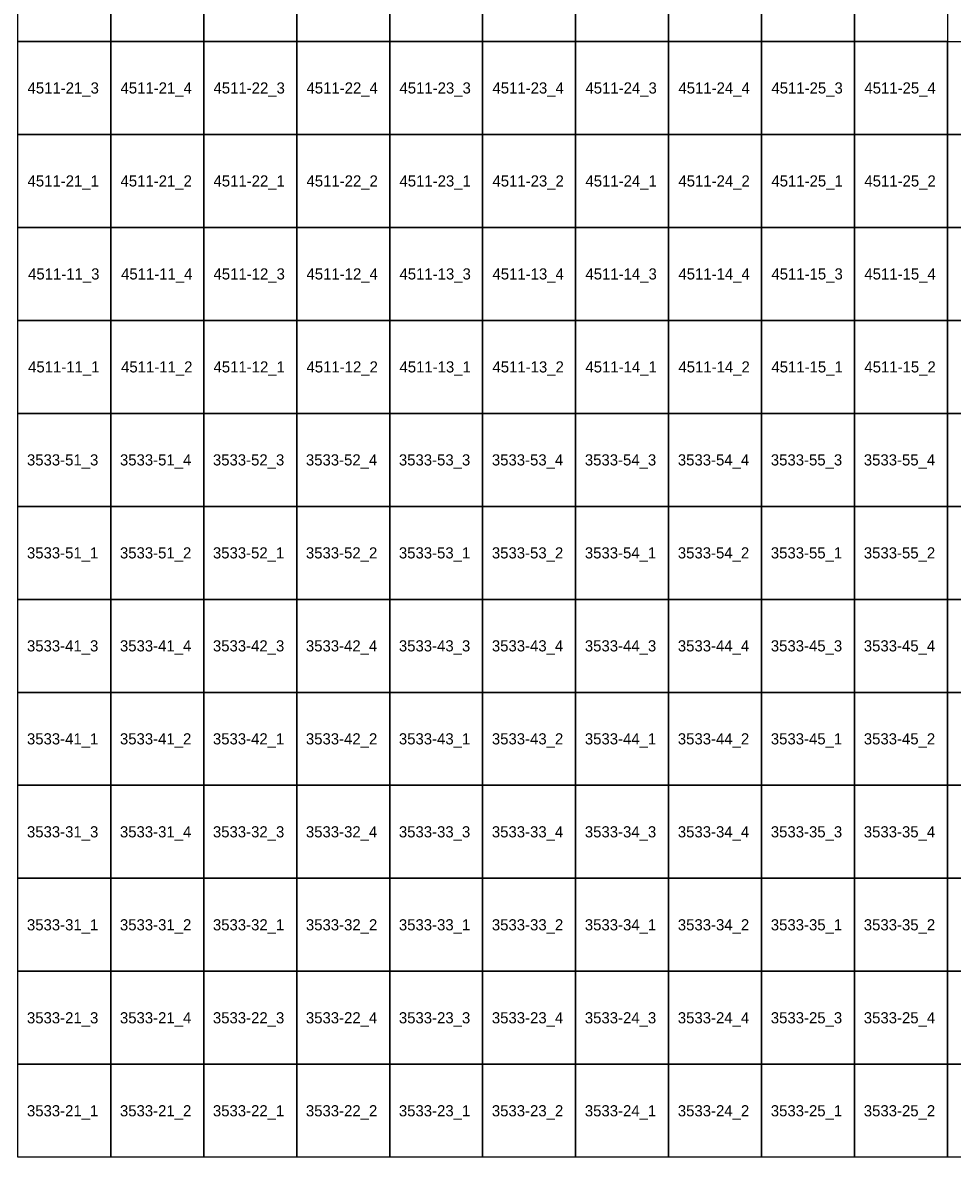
# Model space of a CAD drawing. Extents: x 312500 to 765000, y 172500 to 440000.
# Drawn here: x 700132 to 725129, y 280078 to 310507 of the extents above; entities that cross this region are included whole.
import ezdxf

# ---------------------------------------------------------------- set-up
doc = ezdxf.new("R2010")
doc.units = 0
doc.layers.add('Topo5_ramis_TKS2025', color=7, linetype='Continuous')
doc.layers.add('Topo5_ramis_TKS2025_Nr', color=7, linetype='Continuous')

msp = doc.modelspace()

# ---------------------------------------------------------------- linework, layer by layer
at = {"layer": 'Topo5_ramis_TKS2025'}
for points in [[(700000, 310000), (700000, 312500), (702500, 312500), (702500, 310000), (700000, 310000)], [(702500, 310000), (702500, 312500), (705000, 312500), (705000, 310000), (702500, 310000)], [(705000, 310000), (705000, 312500), (707500, 312500), (707500, 310000), (705000, 310000)], [(707500, 310000), (707500, 312500), (710000, 312500), (710000, 310000), (707500, 310000)], [(710000, 310000), (710000, 312500), (712500, 312500), (712500, 310000), (710000, 310000)], [(712500, 310000), (712500, 312500), (715000, 312500), (715000, 310000), (712500, 310000)], [(715000, 310000), (715000, 312500), (717500, 312500), (717500, 310000), (715000, 310000)], [(717500, 310000), (717500, 312500), (720000, 312500), (720000, 310000), (717500, 310000)], [(720000, 310000), (720000, 312500), (722500, 312500), (722500, 310000), (720000, 310000)], [(722500, 310000), (722500, 312500), (725000, 312500), (725000, 310000), (722500, 310000)], [(700000, 307500), (700000, 310000), (702500, 310000), (702500, 307500), (700000, 307500)], [(702500, 307500), (702500, 310000), (705000, 310000), (705000, 307500), (702500, 307500)], [(705000, 307500), (705000, 310000), (707500, 310000), (707500, 307500), (705000, 307500)], [(707500, 307500), (707500, 310000), (710000, 310000), (710000, 307500), (707500, 307500)], [(710000, 307500), (710000, 310000), (712500, 310000), (712500, 307500), (710000, 307500)], [(712500, 307500), (712500, 310000), (715000, 310000), (715000, 307500), (712500, 307500)], [(715000, 307500), (715000, 310000), (717500, 310000), (717500, 307500), (715000, 307500)], [(717500, 307500), (717500, 310000), (720000, 310000), (720000, 307500), (717500, 307500)], [(720000, 307500), (720000, 310000), (722500, 310000), (722500, 307500), (720000, 307500)], [(722500, 307500), (722500, 310000), (725000, 310000), (725000, 307500), (722500, 307500)], [(725000, 307500), (725000, 310000), (727500, 310000), (727500, 307500), (725000, 307500)], [(700000, 305000), (700000, 307500), (702500, 307500), (702500, 305000), (700000, 305000)], [(702500, 305000), (702500, 307500), (705000, 307500), (705000, 305000), (702500, 305000)], [(705000, 305000), (705000, 307500), (707500, 307500), (707500, 305000), (705000, 305000)], [(707500, 305000), (707500, 307500), (710000, 307500), (710000, 305000), (707500, 305000)], [(710000, 305000), (710000, 307500), (712500, 307500), (712500, 305000), (710000, 305000)], [(712500, 305000), (712500, 307500), (715000, 307500), (715000, 305000), (712500, 305000)], [(715000, 305000), (715000, 307500), (717500, 307500), (717500, 305000), (715000, 305000)], [(717500, 305000), (717500, 307500), (720000, 307500), (720000, 305000), (717500, 305000)], [(720000, 305000), (720000, 307500), (722500, 307500), (722500, 305000), (720000, 305000)], [(722500, 305000), (722500, 307500), (725000, 307500), (725000, 305000), (722500, 305000)], [(725000, 305000), (725000, 307500), (727500, 307500), (727500, 305000), (725000, 305000)], [(700000, 302500), (700000, 305000), (702500, 305000), (702500, 302500), (700000, 302500)], [(702500, 302500), (702500, 305000), (705000, 305000), (705000, 302500), (702500, 302500)], [(705000, 302500), (705000, 305000), (707500, 305000), (707500, 302500), (705000, 302500)], [(707500, 302500), (707500, 305000), (710000, 305000), (710000, 302500), (707500, 302500)], [(710000, 302500), (710000, 305000), (712500, 305000), (712500, 302500), (710000, 302500)], [(712500, 302500), (712500, 305000), (715000, 305000), (715000, 302500), (712500, 302500)], [(715000, 302500), (715000, 305000), (717500, 305000), (717500, 302500), (715000, 302500)], [(717500, 302500), (717500, 305000), (720000, 305000), (720000, 302500), (717500, 302500)], [(720000, 302500), (720000, 305000), (722500, 305000), (722500, 302500), (720000, 302500)], [(722500, 302500), (722500, 305000), (725000, 305000), (725000, 302500), (722500, 302500)], [(725000, 302500), (725000, 305000), (727500, 305000), (727500, 302500), (725000, 302500)], [(700000, 300000), (700000, 302500), (702500, 302500), (702500, 300000), (700000, 300000)], [(702500, 300000), (702500, 302500), (705000, 302500), (705000, 300000), (702500, 300000)], [(705000, 300000), (705000, 302500), (707500, 302500), (707500, 300000), (705000, 300000)], [(707500, 300000), (707500, 302500), (710000, 302500), (710000, 300000), (707500, 300000)], [(710000, 300000), (710000, 302500), (712500, 302500), (712500, 300000), (710000, 300000)], [(712500, 300000), (712500, 302500), (715000, 302500), (715000, 300000), (712500, 300000)], [(715000, 300000), (715000, 302500), (717500, 302500), (717500, 300000), (715000, 300000)], [(717500, 300000), (717500, 302500), (720000, 302500), (720000, 300000), (717500, 300000)], [(720000, 300000), (720000, 302500), (722500, 302500), (722500, 300000), (720000, 300000)], [(722500, 300000), (722500, 302500), (725000, 302500), (725000, 300000), (722500, 300000)], [(725000, 300000), (725000, 302500), (727500, 302500), (727500, 300000), (725000, 300000)], [(700000, 297500), (700000, 300000), (702500, 300000), (702500, 297500), (700000, 297500)], [(702500, 297500), (702500, 300000), (705000, 300000), (705000, 297500), (702500, 297500)], [(705000, 297500), (705000, 300000), (707500, 300000), (707500, 297500), (705000, 297500)], [(707500, 297500), (707500, 300000), (710000, 300000), (710000, 297500), (707500, 297500)], [(710000, 297500), (710000, 300000), (712500, 300000), (712500, 297500), (710000, 297500)], [(712500, 297500), (712500, 300000), (715000, 300000), (715000, 297500), (712500, 297500)], [(715000, 297500), (715000, 300000), (717500, 300000), (717500, 297500), (715000, 297500)], [(717500, 297500), (717500, 300000), (720000, 300000), (720000, 297500), (717500, 297500)], [(720000, 297500), (720000, 300000), (722500, 300000), (722500, 297500), (720000, 297500)], [(722500, 297500), (722500, 300000), (725000, 300000), (725000, 297500), (722500, 297500)], [(725000, 297500), (725000, 300000), (727500, 300000), (727500, 297500), (725000, 297500)], [(700000, 295000), (700000, 297500), (702500, 297500), (702500, 295000), (700000, 295000)], [(702500, 295000), (702500, 297500), (705000, 297500), (705000, 295000), (702500, 295000)], [(705000, 295000), (705000, 297500), (707500, 297500), (707500, 295000), (705000, 295000)], [(707500, 295000), (707500, 297500), (710000, 297500), (710000, 295000), (707500, 295000)], [(710000, 295000), (710000, 297500), (712500, 297500), (712500, 295000), (710000, 295000)], [(712500, 295000), (712500, 297500), (715000, 297500), (715000, 295000), (712500, 295000)], [(715000, 295000), (715000, 297500), (717500, 297500), (717500, 295000), (715000, 295000)], [(717500, 295000), (717500, 297500), (720000, 297500), (720000, 295000), (717500, 295000)], [(720000, 295000), (720000, 297500), (722500, 297500), (722500, 295000), (720000, 295000)], [(722500, 295000), (722500, 297500), (725000, 297500), (725000, 295000), (722500, 295000)], [(725000, 295000), (725000, 297500), (727500, 297500), (727500, 295000), (725000, 295000)], [(700000, 292500), (700000, 295000), (702500, 295000), (702500, 292500), (700000, 292500)], [(702500, 292500), (702500, 295000), (705000, 295000), (705000, 292500), (702500, 292500)], [(705000, 292500), (705000, 295000), (707500, 295000), (707500, 292500), (705000, 292500)], [(707500, 292500), (707500, 295000), (710000, 295000), (710000, 292500), (707500, 292500)], [(710000, 292500), (710000, 295000), (712500, 295000), (712500, 292500), (710000, 292500)], [(712500, 292500), (712500, 295000), (715000, 295000), (715000, 292500), (712500, 292500)], [(715000, 292500), (715000, 295000), (717500, 295000), (717500, 292500), (715000, 292500)], [(717500, 292500), (717500, 295000), (720000, 295000), (720000, 292500), (717500, 292500)], [(720000, 292500), (720000, 295000), (722500, 295000), (722500, 292500), (720000, 292500)], [(722500, 292500), (722500, 295000), (725000, 295000), (725000, 292500), (722500, 292500)], [(725000, 292500), (725000, 295000), (727500, 295000), (727500, 292500), (725000, 292500)], [(700000, 290000), (700000, 292500), (702500, 292500), (702500, 290000), (700000, 290000)], [(702500, 290000), (702500, 292500), (705000, 292500), (705000, 290000), (702500, 290000)], [(705000, 290000), (705000, 292500), (707500, 292500), (707500, 290000), (705000, 290000)], [(707500, 290000), (707500, 292500), (710000, 292500), (710000, 290000), (707500, 290000)], [(710000, 290000), (710000, 292500), (712500, 292500), (712500, 290000), (710000, 290000)], [(712500, 290000), (712500, 292500), (715000, 292500), (715000, 290000), (712500, 290000)], [(715000, 290000), (715000, 292500), (717500, 292500), (717500, 290000), (715000, 290000)], [(717500, 290000), (717500, 292500), (720000, 292500), (720000, 290000), (717500, 290000)], [(720000, 290000), (720000, 292500), (722500, 292500), (722500, 290000), (720000, 290000)], [(722500, 290000), (722500, 292500), (725000, 292500), (725000, 290000), (722500, 290000)], [(725000, 290000), (725000, 292500), (727500, 292500), (727500, 290000), (725000, 290000)], [(700000, 287500), (700000, 290000), (702500, 290000), (702500, 287500), (700000, 287500)], [(702500, 287500), (702500, 290000), (705000, 290000), (705000, 287500), (702500, 287500)], [(705000, 287500), (705000, 290000), (707500, 290000), (707500, 287500), (705000, 287500)], [(707500, 287500), (707500, 290000), (710000, 290000), (710000, 287500), (707500, 287500)], [(710000, 287500), (710000, 290000), (712500, 290000), (712500, 287500), (710000, 287500)], [(712500, 287500), (712500, 290000), (715000, 290000), (715000, 287500), (712500, 287500)], [(715000, 287500), (715000, 290000), (717500, 290000), (717500, 287500), (715000, 287500)], [(717500, 287500), (717500, 290000), (720000, 290000), (720000, 287500), (717500, 287500)], [(720000, 287500), (720000, 290000), (722500, 290000), (722500, 287500), (720000, 287500)], [(722500, 287500), (722500, 290000), (725000, 290000), (725000, 287500), (722500, 287500)], [(725000, 287500), (725000, 290000), (727500, 290000), (727500, 287500), (725000, 287500)], [(700000, 285000), (700000, 287500), (702500, 287500), (702500, 285000), (700000, 285000)], [(702500, 285000), (702500, 287500), (705000, 287500), (705000, 285000), (702500, 285000)], [(705000, 285000), (705000, 287500), (707500, 287500), (707500, 285000), (705000, 285000)], [(707500, 285000), (707500, 287500), (710000, 287500), (710000, 285000), (707500, 285000)], [(710000, 285000), (710000, 287500), (712500, 287500), (712500, 285000), (710000, 285000)], [(712500, 285000), (712500, 287500), (715000, 287500), (715000, 285000), (712500, 285000)], [(715000, 285000), (715000, 287500), (717500, 287500), (717500, 285000), (715000, 285000)], [(717500, 285000), (717500, 287500), (720000, 287500), (720000, 285000), (717500, 285000)], [(720000, 285000), (720000, 287500), (722500, 287500), (722500, 285000), (720000, 285000)], [(722500, 285000), (722500, 287500), (725000, 287500), (725000, 285000), (722500, 285000)], [(725000, 285000), (725000, 287500), (727500, 287500), (727500, 285000), (725000, 285000)], [(700000, 282500), (700000, 285000), (702500, 285000), (702500, 282500), (700000, 282500)], [(702500, 282500), (702500, 285000), (705000, 285000), (705000, 282500), (702500, 282500)], [(705000, 282500), (705000, 285000), (707500, 285000), (707500, 282500), (705000, 282500)], [(707500, 282500), (707500, 285000), (710000, 285000), (710000, 282500), (707500, 282500)], [(710000, 282500), (710000, 285000), (712500, 285000), (712500, 282500), (710000, 282500)], [(712500, 282500), (712500, 285000), (715000, 285000), (715000, 282500), (712500, 282500)], [(715000, 282500), (715000, 285000), (717500, 285000), (717500, 282500), (715000, 282500)], [(717500, 282500), (717500, 285000), (720000, 285000), (720000, 282500), (717500, 282500)], [(720000, 282500), (720000, 285000), (722500, 285000), (722500, 282500), (720000, 282500)], [(722500, 282500), (722500, 285000), (725000, 285000), (725000, 282500), (722500, 282500)], [(725000, 282500), (725000, 285000), (727500, 285000), (727500, 282500), (725000, 282500)], [(700000, 280000), (700000, 282500), (702500, 282500), (702500, 280000), (700000, 280000)], [(702500, 280000), (702500, 282500), (705000, 282500), (705000, 280000), (702500, 280000)], [(705000, 280000), (705000, 282500), (707500, 282500), (707500, 280000), (705000, 280000)], [(707500, 280000), (707500, 282500), (710000, 282500), (710000, 280000), (707500, 280000)], [(710000, 280000), (710000, 282500), (712500, 282500), (712500, 280000), (710000, 280000)], [(712500, 280000), (712500, 282500), (715000, 282500), (715000, 280000), (712500, 280000)], [(715000, 280000), (715000, 282500), (717500, 282500), (717500, 280000), (715000, 280000)], [(717500, 280000), (717500, 282500), (720000, 282500), (720000, 280000), (717500, 280000)], [(720000, 280000), (720000, 282500), (722500, 282500), (722500, 280000), (720000, 280000)], [(722500, 280000), (722500, 282500), (725000, 282500), (725000, 280000), (722500, 280000)], [(725000, 280000), (725000, 282500), (727500, 282500), (727500, 280000), (725000, 280000)]]:
    msp.add_lwpolyline(points, dxfattribs=at)

# ---------------------------------------------------------------- texts
at = {"layer": 'Topo5_ramis_TKS2025_Nr'}
for s, p in [('4511-21_3', (700264, 308600)), ('4511-21_4', (702764, 308600)), ('4511-22_3', (705264, 308600)), ('4511-22_4', (707764, 308600)), ('4511-23_3', (710264, 308600)), ('4511-23_4', (712764, 308600)), ('4511-24_3', (715264, 308600)), ('4511-24_4', (717764, 308600)), ('4511-25_3', (720264, 308600)), ('4511-25_4', (722764, 308600)), ('4511-21_1', (700264, 306100)), ('4511-21_2', (702764, 306100)), ('4511-22_1', (705264, 306100)), ('4511-22_2', (707764, 306100)), ('4511-23_1', (710264, 306100)), ('4511-23_2', (712764, 306100)), ('4511-24_1', (715264, 306100)), ('4511-24_2', (717764, 306100)), ('4511-25_1', (720264, 306100)), ('4511-25_2', (722764, 306100)), ('4511-11_3', (700279, 303600)), ('4511-11_4', (702779, 303600)), ('4511-12_3', (705264, 303600)), ('4511-12_4', (707764, 303600)), ('4511-13_3', (710264, 303600)), ('4511-13_4', (712764, 303600)), ('4511-14_3', (715264, 303600)), ('4511-14_4', (717764, 303600)), ('4511-15_3', (720264, 303600)), ('4511-15_4', (722764, 303600)), ('4511-11_1', (700279, 301100)), ('4511-11_2', (702779, 301100)), ('4511-12_1', (705264, 301100)), ('4511-12_2', (707764, 301100)), ('4511-13_1', (710264, 301100)), ('4511-13_2', (712764, 301100)), ('4511-14_1', (715264, 301100)), ('4511-14_2', (717764, 301100)), ('4511-15_1', (720264, 301100)), ('4511-15_2', (722764, 301100)), ('3533-51_3', (700248, 298600)), ('3533-51_4', (702748, 298600)), ('3533-52_3', (705248, 298600)), ('3533-52_4', (707748, 298600)), ('3533-53_3', (710248, 298600)), ('3533-53_4', (712748, 298600)), ('3533-54_3', (715248, 298600)), ('3533-54_4', (717748, 298600)), ('3533-55_3', (720248, 298600)), ('3533-55_4', (722748, 298600)), ('3533-51_1', (700248, 296100)), ('3533-51_2', (702748, 296100)), ('3533-52_1', (705248, 296100)), ('3533-52_2', (707748, 296100)), ('3533-53_1', (710248, 296100)), ('3533-53_2', (712748, 296100)), ('3533-54_1', (715248, 296100)), ('3533-54_2', (717748, 296100)), ('3533-55_1', (720248, 296100)), ('3533-55_2', (722748, 296100)), ('3533-41_3', (700248, 293600)), ('3533-41_4', (702748, 293600)), ('3533-42_3', (705248, 293600)), ('3533-42_4', (707748, 293600)), ('3533-43_3', (710248, 293600)), ('3533-43_4', (712748, 293600)), ('3533-44_3', (715248, 293600)), ('3533-44_4', (717748, 293600)), ('3533-45_3', (720248, 293600)), ('3533-45_4', (722748, 293600)), ('3533-41_1', (700248, 291100)), ('3533-41_2', (702748, 291100)), ('3533-42_1', (705248, 291100)), ('3533-42_2', (707748, 291100)), ('3533-43_1', (710248, 291100)), ('3533-43_2', (712748, 291100)), ('3533-44_1', (715248, 291100)), ('3533-44_2', (717748, 291100)), ('3533-45_1', (720248, 291100)), ('3533-45_2', (722748, 291100)), ('3533-31_3', (700248, 288600)), ('3533-31_4', (702748, 288600)), ('3533-32_3', (705248, 288600)), ('3533-32_4', (707748, 288600)), ('3533-33_3', (710248, 288600)), ('3533-33_4', (712748, 288600)), ('3533-34_3', (715248, 288600)), ('3533-34_4', (717748, 288600)), ('3533-35_3', (720248, 288600)), ('3533-35_4', (722748, 288600)), ('3533-31_1', (700248, 286100)), ('3533-31_2', (702748, 286100)), ('3533-32_1', (705248, 286100)), ('3533-32_2', (707748, 286100)), ('3533-33_1', (710248, 286100)), ('3533-33_2', (712748, 286100)), ('3533-34_1', (715248, 286100)), ('3533-34_2', (717748, 286100)), ('3533-35_1', (720248, 286100)), ('3533-35_2', (722748, 286100)), ('3533-21_3', (700248, 283600)), ('3533-21_4', (702748, 283600)), ('3533-22_3', (705248, 283600)), ('3533-22_4', (707748, 283600)), ('3533-23_3', (710248, 283600)), ('3533-23_4', (712748, 283600)), ('3533-24_3', (715248, 283600)), ('3533-24_4', (717748, 283600)), ('3533-25_3', (720248, 283600)), ('3533-25_4', (722748, 283600)), ('3533-21_1', (700248, 281100)), ('3533-21_2', (702748, 281100)), ('3533-22_1', (705248, 281100)), ('3533-22_2', (707748, 281100)), ('3533-23_1', (710248, 281100)), ('3533-23_2', (712748, 281100)), ('3533-24_1', (715248, 281100)), ('3533-24_2', (717748, 281100)), ('3533-25_1', (720248, 281100)), ('3533-25_2', (722748, 281100))]:
    msp.add_text(s, height=300, dxfattribs=at).set_placement(p)

doc.saveas('drawing.dxf')
